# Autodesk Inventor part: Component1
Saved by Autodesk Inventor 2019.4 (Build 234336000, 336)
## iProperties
Created: 2019-12
Part Number: Component1
Material: Generic
Document SubType Name: Modeling
Designer: Administrator
Density: 1 g/cm^3
Appearance: Default
Title: Component1
Author: Administrator
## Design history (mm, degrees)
feature "Body1"
body "Solid1"
